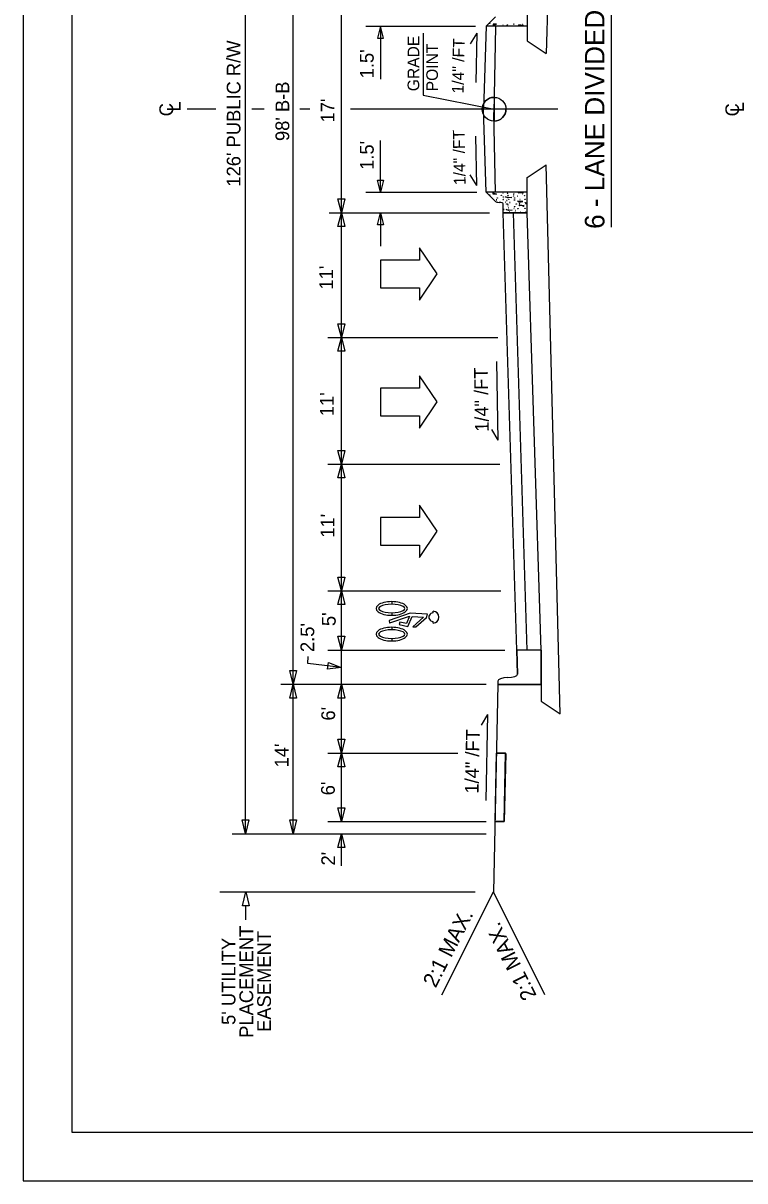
# Model space of a CAD drawing. Extents: x 0 to 8.5, y 0 to 11.
# Drawn here: x 0 to 3.7, y 0 to 5.94 of the extents above; entities that cross this region are included whole.
import ezdxf

# ---------------------------------------------------------------- set-up
doc = ezdxf.new("R2010")
doc.units = 0
for name, color, linetype in [('Level 2', 7, 'Continuous'), ('Level 22', 7, 'Continuous'), ('Level 23', 7, 'Continuous'), ('MARK BICYCLE SYMBOL CELL', 7, 'Continuous'), ('Old_Level_1', 7, 'Continuous'), ('Old_Level_11', 7, 'Continuous'), ('Old_Level_5', 7, 'Continuous'), ('PROP LANE ARROW CELL', 7, 'Continuous'), ('Prop Shade Light', 7, 'Continuous'), ('SHEET BORDER', 7, 'Continuous'), ('SHEET TRIM BORDER', 7, 'Continuous'), ('Typical Curb CELL', 7, 'Continuous'), ('Typical Pavement Slope Information CELL', 7, 'Continuous')]:
    doc.layers.add(name, color=color, linetype=linetype)

msp = doc.modelspace()

# ---------------------------------------------------------------- linework, layer by layer
at = {"layer": 'Level 2'}
msp.add_line((3.016, 6.0442), (3.016, 4.8942), dxfattribs=at)
at = {"layer": 'Level 22'}
for p, q in [((2.4235, 5.9233), (2.4139, 5.4823)), ((2.4152, 5.5607), (2.4152, 5.4996)), ((2.4152, 5.4996), (2.3541, 5.4996)), ((2.4228, 5.0742), (2.4139, 5.4823)), ((2.4152, 5.4996), (2.4152, 5.4385)), ((2.4763, 5.4996), (2.4152, 5.4996))]:
    msp.add_line(p, q, dxfattribs=at)
msp.add_circle((2.4152, 5.4995), 0.0611, dxfattribs=at)
for start, end in [(90, 180), (270, 0)]:
    msp.add_arc((2.4152, 5.4995), 0.0611, start, end, dxfattribs=at)
at = {"layer": 'Level 23'}
for p, q in [((2.3262, 5.8899), (2.2929, 5.8347)), ((2.3262, 5.8899), (2.3212, 5.6362)), ((2.3262, 5.108), (2.3212, 5.3617)), ((2.3262, 5.108), (2.2929, 5.1631)), ((2.4371, 3.8008), (2.429, 4.2044)), ((2.4371, 3.8008), (2.4038, 3.8559)), ((2.3822, 2.3931), (2.3489, 2.338)), ((2.3822, 2.3931), (2.3734, 1.9511))]:
    msp.add_line(p, q, dxfattribs=at)
at = {"layer": 'MARK BICYCLE SYMBOL CELL'}
for p, q in [((1.8904, 2.9725), (1.8904, 2.9594)), ((1.8904, 2.9725), (1.8904, 2.9594)), ((1.9842, 2.913), (1.8769, 2.8752)), ((1.8904, 2.9155), (1.8904, 2.9024)), ((1.8904, 2.9155), (1.8904, 2.9024)), ((2.0739, 2.9077), (1.9842, 2.913)), ((2.1025, 2.9149), (2.1025, 2.9232)), ((2.1025, 2.9149), (2.1025, 2.9232)), ((1.8769, 2.8752), (1.8797, 2.8627)), ((1.8811, 2.8631), (1.9823, 2.8988)), ((1.9319, 2.8674), (1.9292, 2.8549)), ((1.9292, 2.8549), (1.9735, 2.8455)), ((1.966, 2.8601), (1.9319, 2.8674)), ((1.9823, 2.8988), (1.966, 2.8601)), ((1.9735, 2.8455), (1.9948, 2.8958)), ((1.9948, 2.8958), (2.0533, 2.8923)), ((2.0533, 2.8923), (1.9982, 2.8427)), ((2.0148, 2.8427), (2.0688, 2.8908)), ((2.0688, 2.8908), (2.0739, 2.9077)), ((2.1025, 2.8625), (2.1025, 2.8708)), ((2.1025, 2.8625), (2.1025, 2.8708)), ((1.8904, 2.8409), (1.8904, 2.8278)), ((1.8904, 2.8409), (1.8904, 2.8278)), ((1.9982, 2.8427), (2.0148, 2.8427)), ((1.8904, 2.7839), (1.8904, 2.7708)), ((1.8904, 2.7839), (1.8904, 2.7708))]:
    msp.add_line(p, q, dxfattribs=at)
for radius, start, end in [(0.0221, 90.00002, 270.00002), (0.0303, 270.00002, 90.00002), (0.0303, 270.00002, 90.00002)]:
    msp.add_arc((2.1025, 2.8928), radius, start, end, dxfattribs=at)
for centre, major_axis, ratio, start_param, end_param in [((1.8904, 2.9374), (-0.0804, 0), 0.435841, 4.712389, 7.853982), ((1.8904, 2.9374), (-0.0804, 0), 0.435841, 1.570796, 4.712389), ((1.8904, 2.9374), (-0.0673, 0), 0.325967, 4.712389, 7.853982), ((1.8904, 2.9374), (-0.0673, 0), 0.325967, 1.570796, 4.712389), ((1.8904, 2.8058), (-0.0804, 0), 0.435841, 4.712389, 7.853982), ((1.8904, 2.8058), (-0.0673, 0), 0.325967, 4.712389, 7.853982), ((1.8904, 2.8058), (-0.0804, 0), 0.435841, 1.570796, 4.712389), ((1.8904, 2.8058), (-0.0673, 0), 0.325967, 1.570796, 4.712389)]:
    msp.add_ellipse(centre, major_axis=major_axis, ratio=ratio, start_param=start_param, end_param=end_param, dxfattribs=at)
at = {"layer": 'Old_Level_1'}
for p, q in [((2.7552, 8.604), (2.6831, 5.7851)), ((2.3741, 5.9257), (2.3607, 5.5)), ((2.5852, 5.9257), (2.5852, 5.8503)), ((2.5852, 5.8503), (2.6831, 5.7851)), ((2.3741, 5.0742), (2.3607, 5.5)), ((2.5852, 5.1496), (2.6831, 5.2148)), ((2.7552, 2.3959), (2.6831, 5.2148)), ((2.5852, 5.0742), (2.5852, 5.1496)), ((2.5327, 2.7242), (2.4621, 4.9687)), ((2.5852, 2.7242), (2.5146, 4.9687)), ((2.6563, 2.7242), (2.5852, 4.9687)), ((2.6563, 2.7242), (2.5323, 2.7242)), ((2.5362, 2.6005), (2.5323, 2.7242)), ((2.6563, 2.7242), (2.6563, 2.5472)), ((2.6563, 2.7242), (2.6563, 2.5472)), ((2.4341, 2.5649), (2.4341, 2.5472)), ((2.4341, 2.5472), (2.4119, 1.4832)), ((2.6563, 2.5472), (2.4341, 2.5472)), ((2.6563, 2.5472), (2.6563, 2.4619)), ((2.6563, 2.4619), (2.7552, 2.3959)), ((2.1477, 0.9548), (2.4119, 1.4832)), ((2.6761, 0.9548), (2.4119, 1.4832))]:
    msp.add_line(p, q, dxfattribs=at)
for centre, major_axis, ratio, start_param, end_param in [((2.487, 2.5649), (-0.0531, 0), 0.333333, 4.760521, 6.283197), ((2.4819, 2.6003), (-0.0543, 0), 0.32599, 1.618928, 3.151961)]:
    msp.add_ellipse(centre, major_axis=major_axis, ratio=ratio, start_param=start_param, end_param=end_param, dxfattribs=at)
at = {"layer": 'Old_Level_11'}
for p, q in [((1.1402, 1.7813), (1.14, 9.2187)), ((1.3849, 1.7813), (1.3849, 9.2187)), ((1.6322, 4.9687), (1.6322, 6.0313)), ((1.7581, 5.9257), (2.3205, 5.9257)), ((1.8325, 5.9257), (1.8325, 5.6547)), ((2.0511, 5.8899), (2.051, 5.5716)), ((2.051, 5.5716), (2.4152, 5.4996)), ((0.9883, 5.5), (0.8417, 5.5)), ((1.2353, 5.5), (1.1728, 5.5)), ((1.4704, 5.5), (1.4198, 5.5)), ((2.7423, 5.5), (1.6787, 5.5)), ((1.8325, 5.0743), (1.8325, 5.3396)), ((1.7581, 5.0743), (2.3261, 5.0742)), ((1.5692, 4.9687), (2.3927, 4.9687)), ((1.6323, 3.1771), (1.6322, 4.9687)), ((1.8325, 4.9687), (1.8325, 4.7963)), ((1.5635, 4.3281), (2.4341, 4.3281)), ((1.5635, 3.6781), (2.4441, 3.6781)), ((1.6323, 2.5827), (1.6323, 3.1771)), ((1.5635, 3.0281), (2.4507, 3.0281)), ((1.5635, 2.7242), (2.4706, 2.7242)), ((1.6323, 2.1953), (1.6323, 2.5827)), ((1.3223, 2.5482), (2.3744, 2.5482)), ((1.5635, 2.1953), (2.2297, 2.1953)), ((1.6323, 1.8434), (1.6323, 2.1953)), ((2.4753, 2.1929), (2.4279, 2.1929)), ((1.5635, 1.8434), (2.3744, 1.8434)), ((1.0712, 1.7813), (2.3744, 1.7812)), ((1.6323, 1.6161), (1.6323, 1.7813)), ((1.0095, 1.4833), (2.3192, 1.4832)), ((1.1422, 1.34), (1.1422, 1.4121))]:
    msp.add_line(p, q, dxfattribs=at)
for points in [[(1.8479, 5.8641), (1.8325, 5.9257), (1.8171, 5.8641)], [(1.8479, 5.1358), (1.8325, 5.0743), (1.8171, 5.1358)], [(1.6499, 5.0395), (1.6322, 4.9687), (1.6145, 5.0395)], [(1.6145, 4.8979), (1.6322, 4.9687), (1.6499, 4.8979)], [(1.8171, 4.9071), (1.8325, 4.9687), (1.8479, 4.9071)], [(1.6499, 4.3989), (1.6322, 4.3281), (1.6145, 4.3989)], [(1.6145, 4.2573), (1.6322, 4.3281), (1.6499, 4.2573)], [(1.6499, 3.7489), (1.6322, 3.6781), (1.6146, 3.7489)], [(1.6146, 3.6073), (1.6322, 3.6781), (1.6499, 3.6073)], [(1.65, 3.0989), (1.6323, 3.0281), (1.6146, 3.0989)], [(1.6146, 2.9573), (1.6323, 3.0281), (1.65, 2.9573)], [(1.65, 2.795), (1.6323, 2.7242), (1.6146, 2.795)], [(1.4026, 2.619), (1.3849, 2.5482), (1.3672, 2.619)], [(1.5654, 2.66), (1.6309, 2.6351), (1.5614, 2.6263)], [(1.3672, 2.4774), (1.3849, 2.5482), (1.4026, 2.4774)], [(1.6146, 2.4774), (1.6323, 2.5482), (1.65, 2.4774)], [(1.65, 2.2661), (1.6323, 2.1953), (1.6146, 2.2661)], [(1.6146, 2.1245), (1.6323, 2.1953), (1.65, 2.1245)], [(1.65, 1.9142), (1.6323, 1.8434), (1.6146, 1.9142)], [(1.1579, 1.8521), (1.1402, 1.7813), (1.1225, 1.8521)], [(1.4026, 1.8521), (1.3849, 1.7813), (1.3672, 1.8521)], [(1.6146, 1.7105), (1.6323, 1.7813), (1.65, 1.7105)], [(1.1245, 1.4121), (1.1422, 1.4829), (1.1599, 1.4121)]]:
    msp.add_lwpolyline(points, close=True, dxfattribs=at)
msp.add_lwpolyline([(1.6312, 2.6349), (1.4594, 2.6553), (1.4611, 2.6909)], dxfattribs=at)
at = {"layer": 'Old_Level_5'}
for p, q in [((2.4736, 2.1935), (2.4262, 2.1934)), ((2.4753, 2.1929), (2.4673, 1.8434)), ((2.4668, 1.8434), (2.4194, 1.8434))]:
    msp.add_line(p, q, dxfattribs=at)
for points in [[(2.4339, 2.5649), (2.4341, 2.5472), (2.6563, 2.5472), (2.6563, 2.7242), (2.5327, 2.7242)], [(2.5327, 2.7242), (2.5323, 2.7242), (2.5362, 2.6005)], [(2.4845, 2.5826), (2.4845, 2.5826)]]:
    msp.add_lwpolyline(points, dxfattribs=at)
for centre, major_axis, ratio, start_param, end_param in [((2.487, 2.5649), (-0.0531, 0), 0.333333, 4.760521, 6.283197), ((2.4819, 2.6003), (-0.0543, 0), 0.32599, 1.618928, 3.151961)]:
    msp.add_ellipse(centre, major_axis=major_axis, ratio=ratio, start_param=start_param, end_param=end_param, dxfattribs=at)
at = {"layer": 'PROP LANE ARROW CELL'}
for points in [[(2.0322, 4.7887), (2.0322, 4.7246), (1.8326, 4.7246), (1.8326, 4.5835), (2.0322, 4.5835), (2.0322, 4.5193), (2.124, 4.6554), (2.0322, 4.7887)], [(2.0322, 4.1318), (2.0322, 4.0676), (1.8326, 4.0676), (1.8326, 3.9265), (2.0322, 3.9265), (2.0322, 3.8624), (2.124, 3.9984), (2.0322, 4.1318)], [(2.0322, 3.468), (2.0322, 3.4039), (1.8326, 3.4039), (1.8326, 3.2628), (2.0322, 3.2628), (2.0322, 3.1986), (2.124, 3.3346), (2.0322, 3.468)]]:
    msp.add_lwpolyline(points, dxfattribs=at)
at = {"layer": 'Prop Shade Light'}
msp.add_lwpolyline([(2.4267, 2.1953), (2.4194, 1.8434), (2.4673, 1.8434), (2.4742, 2.1953)], close=True, dxfattribs=at)
at = {"layer": 'SHEET BORDER'}
msp.add_lwpolyline([(8.25, 10.75), (0.25, 10.75), (0.25, 0.25), (8.25, 0.25)], close=True, dxfattribs=at)
at = {"layer": 'SHEET TRIM BORDER'}
msp.add_lwpolyline([(8.5, 11), (0, 11), (0, 0), (8.5, 0)], close=True, dxfattribs=at)
at = {"layer": 'Typical Curb CELL'}
for p, q in [((2.5852, 6.0313), (2.5852, 5.9257)), ((2.4224, 5.974), (2.3741, 5.9257)), ((2.5852, 5.9257), (2.3741, 5.9257)), ((2.4104, 5.9361), (2.4104, 5.93)), ((2.4285, 5.9358), (2.4104, 5.9361)), ((2.4104, 5.93), (2.4285, 5.9358)), ((2.541, 5.9319), (2.5439, 5.9268)), ((2.5669, 5.9294), (2.541, 5.9319)), ((2.5439, 5.9268), (2.5669, 5.9294)), ((2.5852, 5.0742), (2.3741, 5.0742)), ((2.4224, 5.026), (2.3741, 5.0742)), ((2.4104, 5.0639), (2.4104, 5.0699)), ((2.4104, 5.0699), (2.4285, 5.0642)), ((2.4285, 5.0642), (2.4104, 5.0639)), ((2.541, 5.0681), (2.5439, 5.0731)), ((2.5669, 5.0706), (2.541, 5.0681)), ((2.5439, 5.0731), (2.5669, 5.0706)), ((2.5852, 4.9687), (2.5852, 5.0742)), ((2.4423, 5.0215), (2.4412, 5.0215)), ((2.4621, 4.9687), (2.4621, 5.0149)), ((2.4743, 5.0499), (2.5059, 5.047)), ((2.4866, 5.0442), (2.4743, 5.0499)), ((2.5059, 5.047), (2.4866, 5.0442)), ((2.5353, 5.0283), (2.5458, 5.0219)), ((2.5629, 5.0261), (2.5353, 5.0283)), ((2.5443, 5.0034), (2.5472, 5.0084)), ((2.5702, 5.0059), (2.5443, 5.0034)), ((2.5458, 5.0219), (2.5629, 5.0261)), ((2.5472, 5.0084), (2.5702, 5.0059)), ((2.4621, 4.9687), (2.5852, 4.9687)), ((2.5852, 4.9687), (2.4634, 4.9687)), ((2.4776, 4.9852), (2.509, 4.9823)), ((2.49, 4.9795), (2.4776, 4.9852)), ((2.509, 4.9823), (2.49, 4.9795))]:
    msp.add_line(p, q, dxfattribs=at)
for centre in [(2.3923, 5.9405), (2.4609, 5.931), (2.4838, 5.9316), (2.5172, 5.9358), (2.5621, 5.9342), (2.3923, 5.0594), (2.4523, 5.0575), (2.4609, 5.069), (2.4838, 5.0683), (2.4867, 5.0579), (2.5143, 5.0547), (2.5172, 5.0642), (2.5344, 5.0537), (2.5621, 5.0658), (2.5706, 5.0556), (2.4275, 5.0346), (2.4323, 5.0442), (2.4619, 5.0359), (2.4628, 5.0493), (2.4752, 5.0226), (2.48, 5.013), (2.4809, 5.0311), (2.4862, 5.0119), (2.4871, 5.0037), (2.49, 4.9932), (2.4905, 5.0375), (2.4962, 5.021), (2.5201, 5.034), (2.5205, 4.9995), (2.521, 5.0442), (2.5291, 5.0135), (2.5458, 5.0146), (2.5487, 5.0362), (2.5654, 5.0011), (2.5739, 4.9909), (2.5744, 5.0372), (2.5754, 5.02), (2.5783, 5.0146), (2.4661, 4.9846), (2.4938, 4.9728), (2.5176, 4.99), (2.5234, 4.9693), (2.5243, 4.9795), (2.5377, 4.989), (2.552, 4.9715), (2.5777, 4.9725)]:
    msp.add_ellipse(centre, major_axis=(0.00134, 0), ratio=0.333333, dxfattribs=at)
for centre, major_axis, start_param, end_param in [((2.584, 5.9281), (0.00134, 0), 2.042708, 4.26282), ((2.584, 5.0718), (0.00134, 0), 2.020366, 4.240477), ((2.4412, 5.0281), (-0.0198, 0), 0.321751, 1.570796), ((2.4423, 5.0149), (-0.0198, 0), 3.141593, 4.712389)]:
    msp.add_ellipse(centre, major_axis=major_axis, ratio=0.333333, start_param=start_param, end_param=end_param, dxfattribs=at)

# ---------------------------------------------------------------- texts
at = {"layer": 'Level 2'}
msp.add_text('6 - LANE DIVIDED', height=0.100219, rotation=90, dxfattribs=at).set_placement((2.9814, 4.8855))
at = {"layer": 'Old_Level_11'}
for s, height, rotation, p in [("126' PUBLIC R/W", 0.070389, 90.00211, (1.1147, 5.1024)), ('GRADE', 0.05983, 89.99789, (2.0316, 5.592)), ('POINT', 0.05983, 89.99789, (2.1275, 5.5916)), ("1.5'", 0.07039, 90, (1.798, 5.658)), ("98' B-B", 0.07039, 90.00211, (1.3647, 5.3363)), ('C', 0.0708, 89.99789, (0.7694, 5.463)), ('L', 0.0708, 89.94479, (0.8078, 5.4879)), ("17'", 0.07039, 89.99789, (1.5966, 5.4316)), ('C', 0.07, 89.99789, (3.6719, 5.4626)), ('L', 0.07, 89.94479, (3.6965, 5.484)), ("1.5'", 0.07039, 90, (1.798, 5.1883)), ("11'", 0.07039, 90.00211, (1.5894, 4.5741)), ("11'", 0.07039, 90.00211, (1.5927, 3.9242)), ("11'", 0.07039, 90.00211, (1.596, 3.3007)), ("5'", 0.07039, 90.00211, (1.603, 2.847)), ("2.5'", 0.07039, 90, (1.4929, 2.7138)), ("6'", 0.07039, 90.00211, (1.5998, 2.3622)), ("14'", 0.07039, 90, (1.361, 2.1217)), ("6'", 0.07039, 90.00211, (1.5983, 1.9787)), ("2'", 0.07039, 90.00211, (1.5998, 1.6183)), ('2:1 MAX.', 0.07821, 62.953, (2.1157, 0.9864)), ('2:1 MAX.', 0.07821, 117.047, (2.6354, 0.9512)), ('PLACEMENT', 0.07039, 90, (1.1798, 0.7339)), ('EASEMENT', 0.07039, 90, (1.2709, 0.7643)), ("5' UTILITY", 0.07039, 90, (1.0887, 0.8001))]:
    msp.add_text(s, height=height, rotation=rotation, dxfattribs=at).set_placement(p)
at = {"layer": 'Typical Pavement Slope Information CELL'}
for height, rotation, p in [(0.06, 88.85215, (2.2592, 5.58)), (0.06, 91.14785, (2.2694, 5.1111)), (0.07, 91.14785, (2.3887, 3.8449)), (0.07, 88.85215, (2.3353, 1.987))]:
    msp.add_text('1/4" /FT', height=height, rotation=rotation, dxfattribs=at).set_placement(p)

doc.saveas('drawing.dxf')
